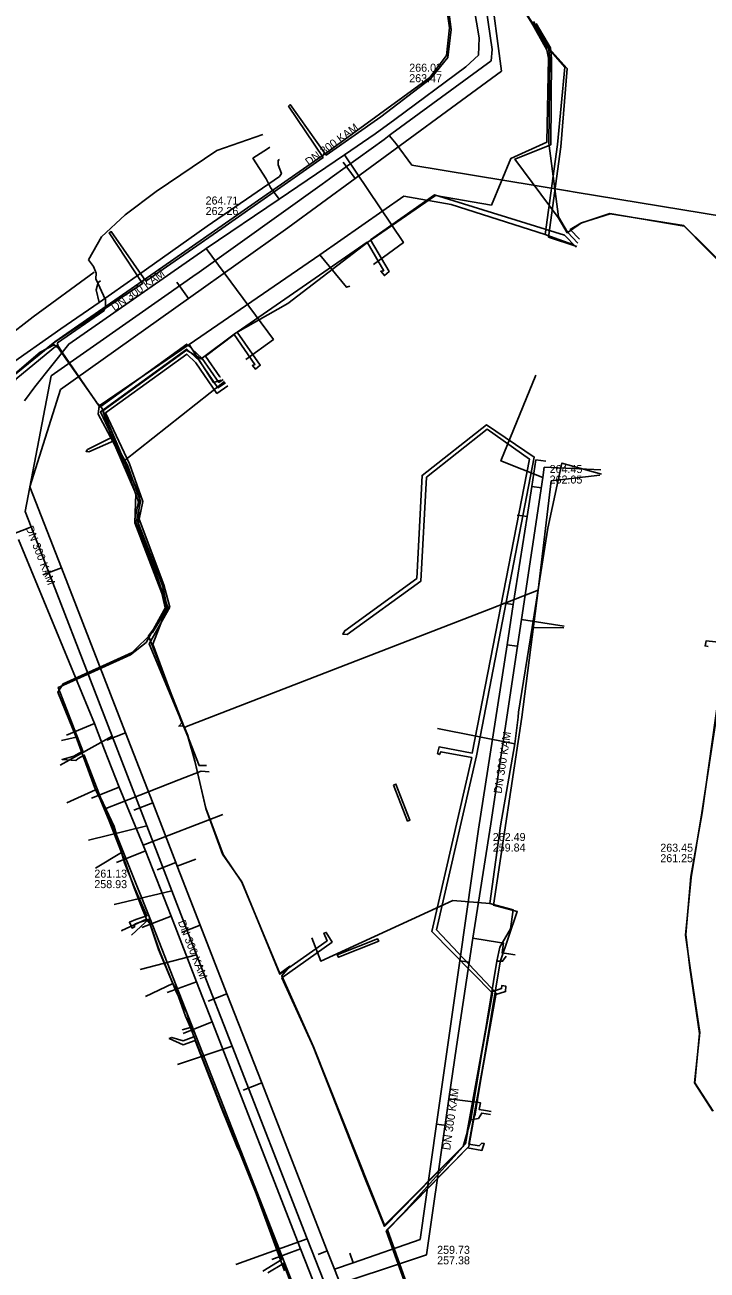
# Model space of a CAD drawing. Extents: x -598233 to -596890, y -1157848 to -1156431.
# Drawn here: x -598097.6 to -598029.4, y -1156997.4 to -1156873 of the extents above; entities that cross this region are included whole.
import ezdxf

# ---------------------------------------------------------------- set-up
doc = ezdxf.new("R2010")
doc.units = 0
for name, color, linetype in [('Vrstva 12', 7, 'Continuous'), ('Vrstva 13', 7, 'Continuous'), ('Vrstva 16', 7, 'Continuous'), ('Vrstva 3', 7, 'Continuous'), ('Vrstva 42', 7, 'Continuous'), ('Vrstva 5', 7, 'Continuous'), ('Vrstva 55', 7, 'Continuous'), ('Vrstva 58', 7, 'Continuous'), ('Vrstva 8', 7, 'Continuous')]:
    doc.layers.add(name, color=color, linetype=linetype)

msp = doc.modelspace()

# ---------------------------------------------------------------- linework, layer by layer
at = {"layer": 'Vrstva 12'}
for points in [[(-598044.45, -1156850.8), (-598047.26, -1156851.21), (-598048.23, -1156851.76), (-598049.21, -1156852.73), (-598048.98, -1156865), (-598047.86, -1156871.42), (-598045.54, -1156875.13), (-598043.67, -1156877.25), (-598044.4, -1156884.96), (-598045.62, -1156893.97)], [(-598090.19, -1156900.77), (-598086.49, -1156898.17), (-598079.41, -1156893.12), (-598072.19, -1156888.17), (-598071.99, -1156887.87), (-598072.31, -1156887.01), (-598072.3, -1156886.55), (-598072.17, -1156886.46)], [(-598045.62, -1156893.97), (-598055.02, -1156890.98), (-598059.75, -1156890.14), (-598068.14, -1156896)], [(-598044.72, -1156894.3), (-598045.62, -1156893.97)], [(-598042.87, -1156894.96), (-598044.72, -1156894.3)], [(-598068.14, -1156896), (-598081.19, -1156904.96)], [(-598068.14, -1156896), (-598065.48, -1156899.24), (-598065.16, -1156899.13)], [(-598090.19, -1156900.77), (-598090.5, -1156899.51), (-598090.3, -1156898.75), (-598090.07, -1156898.6)], [(-598090.19, -1156900.77), (-598094.03, -1156903.4)], [(-598094.03, -1156903.4), (-598099.52, -1156907.27), (-598106.33, -1156912.51), (-598110.77, -1156915.62), (-598116.89, -1156920.15), (-598121.04, -1156923.03), (-598121.83, -1156922.93), (-598122.39, -1156922.32), (-598122.7, -1156921.81)], [(-598088.63, -1156915.03), (-598090.29, -1156911.93), (-598090.2, -1156911.1), (-598089.38, -1156910.53), (-598081.19, -1156904.96)], [(-598081.19, -1156904.96), (-598078.76, -1156908.76), (-598078.02, -1156908.53)], [(-598092.49, -1156944.21), (-598094.32, -1156939.7), (-598093.81, -1156938.86), (-598086.9, -1156935.73), (-598084.87, -1156933.72), (-598083.84, -1156932.07), (-598083.6, -1156931.28), (-598083.95, -1156929.82), (-598086.64, -1156922.79), (-598086.53, -1156919.89), (-598088.63, -1156915.03)], [(-598046.92, -1156933.22), (-598045.36, -1156923.31), (-598043.95, -1156916.81), (-598040.01, -1156917.91)], [(-598046.92, -1156933.22), (-598048.28, -1156941.68), (-598048.34, -1156942.2)], [(-598046.92, -1156933.22), (-598043.77, -1156933.28)], [(-598048.34, -1156942.2), (-598048.66, -1156944.87)], [(-598093.97, -1156944.54), (-598092.49, -1156944.21)], [(-598090.56, -1156949.44), (-598092.49, -1156944.21)], [(-598048.66, -1156944.87), (-598056.39, -1156943.32)], [(-598051.16, -1156960.83), (-598050.1, -1156953.06), (-598048.66, -1156944.87)], [(-598093.42, -1156950.77), (-598090.56, -1156949.44)], [(-598090.56, -1156949.44), (-598090.19, -1156950.16), (-598089.19, -1156952.56), (-598087.95, -1156955.72)], [(-598087.95, -1156955.72), (-598090.57, -1156957.29)], [(-598086.03, -1156960.98), (-598086.81, -1156958.97), (-598087.73, -1156956.33), (-598087.95, -1156955.72)], [(-598051.16, -1156960.83), (-598054.84, -1156960.52), (-598068.05, -1156966.57), (-598068.96, -1156964.25)], [(-598085.48, -1156962.37), (-598086.03, -1156960.98)], [(-598050.46, -1156966.57), (-598050.17, -1156965.17), (-598049.09, -1156963.33), (-598048.82, -1156961.45), (-598051.16, -1156960.83)], [(-598085.48, -1156962.37), (-598087.93, -1156963.51), (-598087.94, -1156963.57)], [(-598085.48, -1156962.37), (-598085.1, -1156962.89), (-598084.18, -1156965.53), (-598082.85, -1156968.81)], [(-598053.06, -1156982.44), (-598050.46, -1156966.57)], [(-598050.46, -1156966.57), (-598049.88, -1156966.59), (-598049.52, -1156966.09)], [(-598082.85, -1156968.81), (-598085.58, -1156970.12)], [(-598082.85, -1156968.81), (-598082.56, -1156969.28), (-598081.57, -1156972.06), (-598081.07, -1156973.22)], [(-598081.07, -1156973.22), (-598081.89, -1156973.44)], [(-598081.07, -1156973.22), (-598078.12, -1156980.8), (-598074.5, -1156989.79), (-598071.67, -1156997.53)], [(-598053.06, -1156982.44), (-598052.3, -1156982.3), (-598051.97, -1156981.76), (-598051.1, -1156981.9)], [(-598053.06, -1156982.44), (-598053.83, -1156985.09), (-598059.81, -1156991.76), (-598061.51, -1156993.52), (-598059.76, -1156998.41)]]:
    msp.add_lwpolyline(points, dxfattribs=at)
at = {"layer": 'Vrstva 13'}
for p, q in [((-598061.22, -1156884.06), (-598060.94, -1156883.86)), ((-598061.22, -1156884.06), (-598061.01, -1156884.32)), ((-598097, -1156923.19), (-598097.28, -1156923.3)), ((-598088.89, -1156944.11), (-598094.08, -1156947)), ((-598085.45, -1156953.05), (-598091.27, -1156954.47)), ((-598082.95, -1156959.54), (-598088.7, -1156960.92)), ((-598080.47, -1156965.95), (-598086.09, -1156967.4)), ((-598076.91, -1156975.08), (-598082.37, -1156976.89)), ((-598069.4, -1156994.32), (-598076.53, -1156996.9))]:
    msp.add_line(p, q, dxfattribs=at)
for points in [[(-598060.94, -1156883.86), (-598051.02, -1156876.61), (-598050.93, -1156875.49), (-598053.35, -1156858.84), (-598055.24, -1156845.76)], [(-598097, -1156923.19), (-598097.59, -1156921.66), (-598095.01, -1156908.09), (-598083.64, -1156900.14), (-598080.5, -1156897.94), (-598080.43, -1156897.89), (-598067.9, -1156888.93), (-598067.19, -1156888.42), (-598066.91, -1156888.22), (-598061.72, -1156884.46), (-598061.22, -1156884.06)], [(-598061.01, -1156884.32), (-598060.51, -1156884.92), (-598058.94, -1156887.04), (-598043.39, -1156889.59), (-598042.62, -1156889.72), (-598017.03, -1156893.93), (-598016.38, -1156894.04)], [(-598025.45, -1157036.31), (-598026.1, -1157036.32), (-598042.77, -1157036.77), (-598056.75, -1157026.97), (-598056.83, -1157026.76), (-598060.19, -1157017.99), (-598061.19, -1157015.34), (-598062.82, -1157011.17), (-598065.22, -1157005.02), (-598067.75, -1156998.56), (-598069.4, -1156994.32), (-598076.91, -1156975.08), (-598080, -1156967.15), (-598080.47, -1156965.95), (-598082.95, -1156959.54), (-598083.71, -1156957.56), (-598085.45, -1156953.05), (-598087.93, -1156946.58), (-598088.89, -1156944.11), (-598097, -1156923.19)], [(-598097.28, -1156923.3), (-598097.88, -1156923.53), (-598101.9, -1156925.08), (-598112.53, -1156929.68), (-598118.13, -1156932.36), (-598121.12, -1156935.86), (-598122.53, -1156937.52), (-598125.38, -1156940.92), (-598126.18, -1156941.87), (-598128.36, -1156950.3), (-598129.79, -1156955.82), (-598133.18, -1156968.32), (-598137, -1156982.44), (-598137.89, -1156985.7), (-598135.42, -1156990.28), (-598135.28, -1156990.52), (-598124.79, -1157008.96)]]:
    msp.add_lwpolyline(points, dxfattribs=at)
at = {"layer": 'Vrstva 16'}
for points in [[(-598056.79, -1156844.66), (-598053.27, -1156868.21), (-598052.23, -1156874.3), (-598052.3, -1156876.06), (-598053.57, -1156877.21), (-598060.65, -1156882.46), (-598062.61, -1156883.9), (-598065.67, -1156885.99), (-598072.22, -1156890.45), (-598079.51, -1156895.38), (-598079.65, -1156895.47), (-598093.24, -1156904.92), (-598096.62, -1156909.18), (-598097.65, -1156910.59)], [(-598072.22, -1156890.45), (-598073.06, -1156889.26), (-598073.51, -1156888.42), (-598074.83, -1156886.35), (-598073.37, -1156885.39), (-598073.15, -1156885.24)], [(-598065.67, -1156885.99), (-598059.79, -1156894.77), (-598062.78, -1156896.97)], [(-598079.51, -1156895.38), (-598072.78, -1156904.45), (-598075.55, -1156906.47)], [(-598101.79, -1156906.09), (-598101.12, -1156905.63), (-598099.62, -1156904.39), (-598096.78, -1156902.18), (-598090.7, -1156897.72)], [(-598045.86, -1156918.24), (-598050.04, -1156916.59), (-598046.56, -1156908.01)], [(-598068.41, -1156999.56), (-598057.48, -1156995.92), (-598055.69, -1156983.37), (-598055.25, -1156980.32), (-598054.5, -1156975.1), (-598052.84, -1156964.29), (-598051.07, -1156952.84), (-598048, -1156932.45), (-598045.86, -1156918.24), (-598045.71, -1156917.22)], [(-598045.71, -1156917.22), (-598040.06, -1156917.49)], [(-598098.27, -1156924.44), (-598090.67, -1156942.84), (-598089.67, -1156945.45), (-598088.21, -1156949.19), (-598085.79, -1156954.98), (-598085.56, -1156955.54), (-598082.99, -1156962.09), (-598080.46, -1156968.65), (-598078.92, -1156972.64), (-598070.09, -1156995.32), (-598068.41, -1156999.56)], [(-598048, -1156932.45), (-598043.74, -1156933.09)], [(-598090.67, -1156942.84), (-598093.45, -1156943.99)], [(-598088.21, -1156949.19), (-598090.98, -1156950.3)], [(-598085.79, -1156954.98), (-598077.85, -1156951.93)], [(-598085.56, -1156955.54), (-598088.47, -1156956.72)], [(-598082.99, -1156962.09), (-598085.93, -1156963.21)], [(-598052.84, -1156964.29), (-598050.18, -1156964.7), (-598049.78, -1156964.76), (-598049.93, -1156965.75), (-598049.28, -1156965.84), (-598048.64, -1156965.95)], [(-598080.46, -1156968.65), (-598083.39, -1156969.7)], [(-598078.92, -1156972.64), (-598081.79, -1156973.79)], [(-598055.25, -1156980.32), (-598052.26, -1156980.7), (-598052.1, -1156980.72), (-598052.21, -1156981.41), (-598051.59, -1156981.49), (-598051.02, -1156981.59)], [(-598070.09, -1156995.32), (-598072.95, -1156996.38)]]:
    msp.add_lwpolyline(points, dxfattribs=at)
at = {"layer": 'Vrstva 3'}
for points in [[(-598060.77, -1156948.98), (-598060.54, -1156948.88), (-598059.14, -1156952.48), (-598059.37, -1156952.58)], [(-598066.4, -1156965.96), (-598062.37, -1156964.36), (-598062.26, -1156964.59), (-598066.29, -1156966.19)]]:
    msp.add_lwpolyline(points, close=True, dxfattribs=at)
at = {"layer": 'Vrstva 42'}
for points in [[(-598098.85, -1156908.16), (-598094.58, -1156904.68), (-598085.86, -1156898.87), (-598089.2, -1156893.8), (-598088.99, -1156893.67), (-598085.53, -1156898.64), (-598077.93, -1156893.37), (-598067.82, -1156886.26), (-598071.27, -1156881.13), (-598071.12, -1156880.99), (-598067.5, -1156886.03), (-598062.06, -1156882.2), (-598057.07, -1156878.42), (-598055.35, -1156876.29), (-598055.01, -1156873.49), (-598056.15, -1156864.8)], [(-598042.37, -1156894.82), (-598043.41, -1156893.74), (-598044.31, -1156892.2), (-598045.25, -1156884.84), (-598045.16, -1156876.36), (-598045.3, -1156875.33), (-598046.8, -1156872.68)], [(-598078.06, -1156908.14), (-598078.13, -1156908.19), (-598079.57, -1156906.11), (-598076.72, -1156903.95), (-598074.64, -1156906.95), (-598074.88, -1156907.06), (-598074.58, -1156907.42), (-598074.1, -1156907.03), (-598076.4, -1156903.72), (-598063.42, -1156894.74), (-598061.75, -1156897.59), (-598062.05, -1156897.64), (-598061.69, -1156898.07), (-598061.23, -1156897.67), (-598063.09, -1156894.51), (-598056.69, -1156890.01), (-598043.7, -1156894.02), (-598042.53, -1156895.23)], [(-598027.29, -1156897.64), (-598031.74, -1156893.14), (-598039.17, -1156891.88), (-598042.05, -1156892.85), (-598043.12, -1156893.46), (-598042.21, -1156894.42)], [(-598145.59, -1156893.57), (-598145.24, -1156893.42), (-598144.6, -1156893.14), (-598143.07, -1156895.02), (-598145.63, -1156897.92), (-598143.4, -1156899.22), (-598139.81, -1156901.86), (-598138.4, -1156904.61), (-598133.82, -1156908.55), (-598129.01, -1156915.72), (-598124.26, -1156919.78), (-598120.46, -1156925.22), (-598105.22, -1156919.22), (-598100.91, -1156913.6), (-598098.53, -1156908.42), (-598094.35, -1156905), (-598093.94, -1156905.7), (-598090.14, -1156911.23), (-598081.45, -1156904.92), (-598079.9, -1156906.34), (-598078.23, -1156908.74), (-598077.82, -1156908.46)], [(-598077.58, -1156908.78), (-598078.33, -1156909.3), (-598080.22, -1156906.56), (-598081.45, -1156905.42), (-598090.06, -1156911.67), (-598087.55, -1156917.03), (-598086.27, -1156920.67), (-598086.63, -1156922.46), (-598084.11, -1156929.08), (-598083.54, -1156931.16), (-598085.5, -1156934.72), (-598087.08, -1156935.96), (-598093.15, -1156938.73), (-598094.29, -1156939.22), (-598091.82, -1156945.6), (-598092.48, -1156945.96), (-598092.74, -1156946.1), (-598093.9, -1156946.41), (-598092.54, -1156946.51), (-598092.3, -1156946.32), (-598091.68, -1156945.98), (-598090.06, -1156950.21), (-598088.7, -1156953.13), (-598087.66, -1156956.75), (-598086.71, -1156959.14), (-598085.43, -1156962.04), (-598086.53, -1156962.41), (-598087.18, -1156962.68), (-598086.9, -1156963.27), (-598086.66, -1156963.16), (-598086.64, -1156962.89), (-598086.39, -1156962.79), (-598085.28, -1156962.41), (-598084.93, -1156963.4), (-598084.27, -1156965.42), (-598082.44, -1156969.77), (-598081.42, -1156971.73), (-598080.74, -1156974.14), (-598081.79, -1156974.53), (-598082.92, -1156974.2), (-598083.2, -1156974.31), (-598081.8, -1156974.95), (-598080.62, -1156974.52), (-598078.03, -1156981.09), (-598076.43, -1156985.06), (-598075.97, -1156986.02), (-598074.42, -1156990), (-598071.93, -1156996.4), (-598073.83, -1156997.56)], [(-598057.57, -1157004.25), (-598061.46, -1156993.43), (-598053.4, -1156985.23), (-598051.94, -1156985.48), (-598051.72, -1156984.8), (-598051.97, -1156984.77), (-598052.22, -1156985.02), (-598053.24, -1156984.85), (-598050.55, -1156969.9), (-598049.58, -1156969.61), (-598049.57, -1156969.07), (-598049.97, -1156969.01), (-598049.98, -1156969.31), (-598050.89, -1156969.6), (-598053.66, -1156984.91), (-598061.68, -1156993.08), (-598063.61, -1156988.33), (-598068.82, -1156975.1), (-598071.94, -1156968.24), (-598066.92, -1156964.67), (-598067.5, -1156963.71), (-598067.73, -1156963.79), (-598067.42, -1156964.53), (-598072.14, -1156967.89), (-598075.93, -1156958.66), (-598077.88, -1156955.87), (-598079.54, -1156951.32), (-598080.64, -1156946.57), (-598081.32, -1156944.13), (-598085.2, -1156934.87), (-598083.12, -1156931.22), (-598083.73, -1156928.96), (-598086.21, -1156922.42), (-598085.85, -1156920.64), (-598087.18, -1156916.87), (-598089.56, -1156911.8), (-598081.45, -1156905.92), (-598080.55, -1156906.79), (-598078.43, -1156909.85), (-598077.35, -1156909.1)], [(-598029.34, -1156935.13), (-598029.64, -1156935.07), (-598029.55, -1156934.58), (-598027.96, -1156934.72)], [(-598028.84, -1156981.58), (-598030.66, -1156978.75), (-598030.19, -1156973.8), (-598031.18, -1156967.25), (-598031.58, -1156963.91), (-598031.06, -1156958.12), (-598029.95, -1156951.76), (-598028.26, -1156939.92)], [(-598073.33, -1156997.72), (-598071.79, -1156996.78), (-598069.52, -1157002.82)]]:
    msp.add_lwpolyline(points, dxfattribs=at)
at = {"layer": 'Vrstva 5'}
for p, q in [((-598065.81, -1156886.75), (-598064.63, -1156888.37)), ((-598082.43, -1156898.72), (-598081.27, -1156900.35)), ((-598094.06, -1156909.45), (-598097.11, -1156919.17)), ((-598045.57, -1156916.63), (-598046.56, -1156916.48)), ((-598045.99, -1156919.29), (-598046.97, -1156919.14)), ((-598048.43, -1156922), (-598047.44, -1156922.15)), ((-598095.84, -1156927.98), (-598093.97, -1156927.26)), ((-598049.8, -1156930.79), (-598048.81, -1156930.94)), ((-598048.45, -1156935.11), (-598049.43, -1156934.96)), ((-598089.43, -1156944.49), (-598087.57, -1156943.77)), ((-598086.72, -1156951.49), (-598084.85, -1156950.76)), ((-598084.41, -1156957.44), (-598082.54, -1156956.72)), ((-598080.53, -1156956.37), (-598082.4, -1156957.09)), ((-598081.97, -1156963.71), (-598080.1, -1156962.98)), ((-598053.17, -1156966.68), (-598054.16, -1156966.54)), ((-598079.29, -1156970.56), (-598077.43, -1156969.84)), ((-598075.82, -1156979.48), (-598073.95, -1156978.75)), ((-598055.49, -1156983.01), (-598056.48, -1156982.87)), ((-598068.32, -1156995.89), (-598067.41, -1156995.53)), ((-598065.14, -1156995.77), (-598064.81, -1156996.72))]:
    msp.add_line(p, q, dxfattribs=at)
for points in [[(-598053.73, -1156849.4), (-598051.15, -1156868.81), (-598049.98, -1156877.63)], [(-598049.98, -1156877.63), (-598064.63, -1156888.37), (-598071.34, -1156893.29)], [(-598071.34, -1156893.29), (-598081.27, -1156900.35), (-598094.06, -1156909.45)], [(-598046.56, -1156916.48), (-598046.97, -1156919.14), (-598047.44, -1156922.15), (-598048.81, -1156930.94), (-598049.43, -1156934.96), (-598052.3, -1156953.39)], [(-598097.11, -1156919.17), (-598093.97, -1156927.26), (-598087.57, -1156943.77), (-598084.85, -1156950.76), (-598082.54, -1156956.72), (-598082.4, -1156957.09), (-598082.11, -1156957.84)], [(-598052.3, -1156953.39), (-598054.16, -1156966.54), (-598056.48, -1156982.87), (-598058.11, -1156994.39)], [(-598082.11, -1156957.84), (-598080.1, -1156962.98), (-598077.43, -1156969.84), (-598073.95, -1156978.75), (-598067.41, -1156995.52), (-598067.41, -1156995.53), (-598066.67, -1156997.36)], [(-598058.11, -1156994.39), (-598064.81, -1156996.72), (-598066.67, -1156997.36)], [(-598066.67, -1156997.36), (-598064.75, -1157002.27), (-598064.71, -1157002.39), (-598063.42, -1157005.62), (-598063.37, -1157005.75), (-598062.32, -1157008.54), (-598062.31, -1157008.56), (-598059.75, -1157015.01), (-598059.71, -1157015.11), (-598057.58, -1157020.65), (-598057.51, -1157020.83), (-598057.23, -1157021.5), (-598057.19, -1157021.58), (-598055.29, -1157026.46)]]:
    msp.add_lwpolyline(points, dxfattribs=at)
at = {"layer": 'Vrstva 55'}
for points in [[(-598057.35, -1156814.71), (-598057.77, -1156815.46), (-598057.58, -1156816.47), (-598058.45, -1156817.48), (-598059.31, -1156819.26), (-598060.08, -1156822.28), (-598059.22, -1156838.18), (-598057.35, -1156855.48), (-598055.57, -1156870.51), (-598055.19, -1156873.3), (-598055.48, -1156876.08), (-598057.16, -1156878.29), (-598067.59, -1156885.87), (-598083.83, -1156897.21), (-598094.63, -1156904.69), (-598098.81, -1156908.1)], [(-598057.39, -1157004.64), (-598061.38, -1156993.42), (-598053.25, -1156985.08), (-598050.52, -1156969.78), (-598056.47, -1156963.43), (-598052.49, -1156946.06), (-598046.72, -1156916.21), (-598051.48, -1156912.99), (-598057.92, -1156918.04), (-598058.45, -1156928.33), (-598065.65, -1156933.56), (-598065.85, -1156933.9), (-598065.41, -1156933.95), (-598058.06, -1156928.61), (-598057.48, -1156918.23), (-598051.43, -1156913.43), (-598047.2, -1156916.41), (-598052.92, -1156945.79), (-598056.23, -1156945.17), (-598056.38, -1156945.84), (-598056.19, -1156945.94), (-598056.04, -1156945.65), (-598052.97, -1156946.23), (-598056.96, -1156963.6), (-598050.9, -1156969.78), (-598053.59, -1156984.84), (-598061.67, -1156992.96), (-598068.78, -1156975.13), (-598071.95, -1156968.05), (-598071.13, -1156967.08), (-598072.14, -1156967.81), (-598075.94, -1156958.67), (-598077.81, -1156955.91), (-598079.54, -1156951.3), (-598080.65, -1156946.59), (-598081.32, -1156944.04), (-598081.75, -1156943.06), (-598082.23, -1156943.1), (-598081.95, -1156942.77), (-598084.83, -1156934.91), (-598083.39, -1156931.21), (-598083.87, -1156929.05), (-598086.42, -1156922.46), (-598086.08, -1156920.64), (-598087.38, -1156917.03), (-598088.72, -1156914.58), (-598091.22, -1156915.69), (-598091.51, -1156915.64), (-598091.37, -1156915.45), (-598088.96, -1156914.24), (-598089.83, -1156911.58), (-598081.47, -1156905.52), (-598080.02, -1156906.39), (-598076.56, -1156903.84), (-598071.33, -1156900.86), (-598063.35, -1156894.73), (-598056.57, -1156890.07), (-598051, -1156891.03), (-598049.07, -1156886.37), (-598045.47, -1156884.74), (-598045.28, -1156876.35), (-598045.47, -1156875.51), (-598047.01, -1156872.72)], [(-598046.53, -1156872.87), (-598045.08, -1156875.32), (-598044.99, -1156876.37), (-598045.06, -1156884.99), (-598048.65, -1156886.43), (-598044.34, -1156892.26), (-598043.44, -1156893.79), (-598042.01, -1156892.8), (-598039.13, -1156891.9), (-598031.77, -1156893.07), (-598027.19, -1156897.56)], [(-598028.18, -1156939.97), (-598029.98, -1156951.77), (-598031.05, -1156958.23), (-598031.59, -1156963.98), (-598031.14, -1156967.25), (-598030.16, -1156973.72), (-598030.7, -1156978.74), (-598028.9, -1156981.53)]]:
    msp.add_lwpolyline(points, dxfattribs=at)
at = {"layer": 'Vrstva 58'}
for points in [[(-598042.47, -1156895.17), (-598045.28, -1156894.23), (-598044.05, -1156885.21), (-598043.44, -1156877.39), (-598045.21, -1156875.38), (-598047.5, -1156871.92), (-598048.75, -1156865.24), (-598049.61, -1156855.07), (-598048.8, -1156852.57), (-598044.87, -1156851.3), (-598040.67, -1156851.13), (-598031.56, -1156851.14), (-598031.28, -1156853.47)], [(-598094.31, -1156905.29), (-598094.7, -1156904.98), (-598096.08, -1156905.74), (-598100.76, -1156909.7), (-598105.22, -1156913.93), (-598111.67, -1156918.51), (-598121.15, -1156924.04), (-598124.03, -1156920.04), (-598130.81, -1156913.61), (-598136.99, -1156905.59), (-598143.39, -1156899.5), (-598145.98, -1156896.73), (-598142.35, -1156892.94), (-598151.5, -1156880.85), (-598153.21, -1156877.32), (-598159.02, -1156874.19)], [(-598091.26, -1156896.5), (-598089.97, -1156894.21), (-598087.61, -1156892.01), (-598084.49, -1156889.66), (-598078.45, -1156885.58), (-598073.85, -1156883.98)], [(-598094.31, -1156905.29), (-598094.35, -1156904.78), (-598089.72, -1156901.61), (-598089.55, -1156901.15), (-598089.55, -1156900.49), (-598090.53, -1156898.4), (-598090.51, -1156897.82), (-598090.75, -1156897.18), (-598091.26, -1156896.5)], [(-598087.71, -1156916.58), (-598089.94, -1156911.28), (-598090.46, -1156910.71), (-598094.31, -1156905.29)], [(-598087.71, -1156916.58), (-598077.67, -1156908.67)], [(-598081.68, -1156943.25), (-598085.28, -1156934.08), (-598083.27, -1156931.39), (-598086.28, -1156922.88), (-598086.18, -1156920), (-598087.71, -1156916.58)], [(-598081.68, -1156943.25), (-598081.48, -1156943.13), (-598066.14, -1156937.19), (-598051.09, -1156931.37), (-598046.32, -1156929.52), (-598045.02, -1156918.59), (-598040.17, -1156918.03)], [(-598046.32, -1156929.52), (-598047.95, -1156942.19), (-598050.8, -1156960.97), (-598048.42, -1156961.61), (-598050.12, -1156966.65), (-598052.4, -1156980.41), (-598052.65, -1156982.05)], [(-598079.48, -1156947.02), (-598080.22, -1156947.04), (-598081.68, -1156943.25)], [(-598085.14, -1156962.29), (-598089.53, -1156951.31), (-598088.15, -1156950.78), (-598082.23, -1156948.46), (-598080.01, -1156947.6), (-598079.22, -1156947.67)], [(-598085.14, -1156962.29), (-598086.95, -1156963.97)], [(-598067.3, -1157007.88), (-598076.04, -1156985.52), (-598085.14, -1156962.29)]]:
    msp.add_lwpolyline(points, dxfattribs=at)

# ---------------------------------------------------------------- texts
at = {"layer": 'Vrstva 8'}
for s, p in [('266.02', (-598059.21, -1156877.7)), ('263.47', (-598059.21, -1156878.75)), ('264.71', (-598079.56, -1156890.97)), ('262.26', (-598079.56, -1156892.02)), ('264.45', (-598045.18, -1156917.8)), ('262.05', (-598045.18, -1156918.85)), ('262.49', (-598050.86, -1156954.57)), ('259.84', (-598050.86, -1156955.62)), ('263.45', (-598034.12, -1156955.64)), ('261.25', (-598034.12, -1156956.69)), ('261.13', (-598090.68, -1156958.23)), ('258.93', (-598090.68, -1156959.28)), ('259.73', (-598056.42, -1156995.82)), ('257.38', (-598056.42, -1156996.87))]:
    msp.add_text(s, height=0.8, dxfattribs=at).set_placement(p)
for rotation, p in [(36.2109, (-598069.24, -1156887.14)), (35.4088, (-598088.65, -1156901.67)), (291.1772, (-598097.56, -1156923.25)), (81.1881, (-598049.99, -1156949.87)), (291.2917, (-598082.35, -1156962.65)), (81.933, (-598055.12, -1156985.5))]:
    msp.add_text('DN 300 KAM', height=0.8, rotation=rotation, dxfattribs=at).set_placement(p)

doc.saveas('drawing.dxf')
